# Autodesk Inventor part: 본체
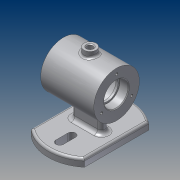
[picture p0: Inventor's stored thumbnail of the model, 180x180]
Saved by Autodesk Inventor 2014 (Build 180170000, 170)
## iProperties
Created: 2017-12
Part Number: 본체
Material: 알루미늄 6061
Document SubType Name: Modeling
Designer: user
Density: 2.71 g/cm^3
Appearance: 알루미늄 - 평지
Author: user
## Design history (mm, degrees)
sketch "스케치1"
  geometry: L1 (35, -42.426)-(35, 42.426); L2 (-35, 42.426)-(-35, -42.426); L3 (-35, 42.426)-(35, 42.426); A1 r 55 centre (0, 0) between (-35, -42.426) and (35, -42.426); A2 r 55 centre (0, 0) between (35, 42.426) and (-35, 42.426); 2 further points
  constraints: 6 end point, 4 point on circle, 2 centre point, 1 coincident, 1 midpoint, 1 parallel, 1 perpendicular, 1 vertical alignment
  dimensions: "d2" = 70 distance between parallel lines of L1 L2; "d3" = 55 radius of A2; "d4" = 55 radius of A1
extrude "돌출1" new body sketch "스케치1" distance "d5" = 10; taper "d6" = 0 deg
sketch "스케치2"
  geometry: L1 (0, 40)-(0, 24); L2 (-5, 40)-(-5, 24); L3 (5, 24)-(5, 40); L4 (0, -24)-(0, -40); L5 (-5, -24)-(-5, -40); L6 (5, -40)-(5, -24); A1 r 5 centre (0, 40) between (5, 40) and (-5, 40); A2 r 5 centre (0, 24) between (-5, 24) and (5, 24); A3 r 5 centre (0, -24) between (5, -24) and (-5, -24); A4 r 5 centre (0, -40) between (-5, -40) and (5, -40); 3 further points
  constraints: 16 end point, 8 point on circle, 8 tangent, 4 centre point, 3 equal length, 2 midpoint, 2 vertical alignment, 1 vertical
  dimensions: "d7" = 16 distance of L1.start L1.end; "d8" = 10 diameter of A2; "d9" = 16 distance of L4.start L4.end; "d10" = 5 radius of A4; "d11" = 24 distance of point (0, 0) L4.start; "d12" = 24 distance of point (0, 0) L1.end
extrude "돌출2" cut sketch "스케치2" distance "d13" = 10; taper "d14" = 0 deg
sketch "스케치3"
  geometry: L1 (-67.128, 62)-(67.128, 62); C1 r 30 at (0, 62); 2 further points
  constraints: 2 end point, 1 centre point, 1 coincident, 1 horizontal, 1 midpoint, 1 vertical alignment
  dimensions: "d15" = 62 distance from line of point (0, 0) L1; "d17" = 60 diameter of C1
extrude "돌출3" join sketch "스케치3" stored distance "d18" = 70; taper "d19" = 0 deg
node "작업 평면1"
sketch "스케치4"
  geometry: C1 r 8 at (0, 0); 1 further point
  constraints: 1 centre point, 1 coincident
  dimensions: "d21" = 16 diameter of C1
extrude "돌출4" join sketch "스케치4" stored distance "d22" = 70; taper "d23" = 0 deg
sketch "스케치5"
  geometry: L1 (-15, 0)-(15, 0); L2 (-15, -5)-(15, -5); L3 (15, 5)-(-15, 5); A1 r 5 centre (-15, 0) between (-15, 5) and (-15, -5); A2 r 5 centre (15, 0) between (15, -5) and (15, 5); 1 further point
  constraints: 8 end point, 4 point on circle, 4 tangent, 2 centre point, 1 horizontal, 1 midpoint, 1 parallel
  dimensions: "d24" = 15 distance of point (0, 0) L1.end; "d25" = 10 diameter of A2
extrude "돌출5" join sketch "스케치5" stored distance "d26" = 70; taper "d27" = 0 deg
sketch "스케치6"
  geometry: L1 (-78.249, 62)-(81.995, 62); L2 (-35, 92)-(-35, 32) reference; L3 (-35, 62)-(-23, 62); L4 (-23, 62)-(-23, 78); L5 (-23, 78)-(-35, 78); L6 (-35, 78)-(-35, 62); L7 (-23, 62)-(-20, 62); L8 (-20, 62)-(-20, 76); L9 (-20, 76)-(-23, 76); L10 (-23, 76)-(-23, 62); L11 (-20, 62)-(20, 62); L12 (20, 62)-(20, 87); L13 (20, 87)-(-20, 87); L14 (-20, 87)-(-20, 62); L15 (20, 62)-(23, 62); L16 (23, 62)-(23, 76); L17 (23, 76)-(20, 76); L18 (20, 76)-(20, 62); L19 (23, 62)-(35, 62); L20 (35, 62)-(35, 78); L21 (35, 78)-(23, 78); L22 (23, 78)-(23, 62); 1 further point
  constraints: 42 end point, 10 parallel, 6 horizontal, 5 perpendicular, 1 midpoint
  dimensions: "d28" = 62 distance from line of point (0, 0) L1; "d29" = 12 distance of L5.end L4.end; "d30" = 16 distance of L4.end L3.end; "d31" = 3 distance of L9.end L8.end; "d32" = 14 distance of L8.end L7.end; "d33" = 40 distance of L13.end L12.end; "d34" = 25 distance of L12.end L11.end; "d35" = 3 distance of L17.end L16.end; "d36" = 14 distance of L16.end L15.end; "d37" = 12 distance of L21.end L20.end; "d38" = 16 distance of L20.end L19.end
revolve "회전1" sketch "스케치6" stored, may be unused: angle "d39" = 90 deg
hole "구멍1" diameter "d42" = 8; stored, may be unused: countersink angle "d46" = 90 deg, drill point angle "d48" = 118 deg; dims "d40" = 10, "d41" = 10, "d43" = 6, "d44" = 4, "d45" = 2, "d47" = 50
sketch "스케치7"
  geometry: C1 r 16 at (0, 0) reference; C2 r 30 at (0, 0) reference; 2 further points
  constraints: 1 horizontal alignment
  dimensions: "d49" = 23 distance of point (-23, 0) C1.centre
hole "구멍2" sketch "스케치7" at (-23, 0) diameter "d50" = 3.459; stored, may be unused: countersink angle "d54" = 90 deg, drill point angle "d56" = 118 deg; dims "d51" = 8, "d52" = 4, "d53" = 2, "d55" = 10
node "작업 평면2"
sketch "스케치9"
  geometry: L1 (-20, -82)-(50, -82) reference; 2 further points
  constraints: 1 vertical alignment, 1 other
  dimensions: "d61" = 30 distance from line of L1 point (15, -52)
feature "엠보싱1" sketch "스케치9" dims "d2" = 70, "d3" = 55, "d4" = 55, "d62" = 0.5, "d63" = 0
fillet "모깎기1" dims "d64" = 0.3
fillet "모깎기2" dims "d65" = 3
fillet "모깎기3" dims "d66" = 5
fillet "모깎기4" dims "d67" = 3
chamfer "모따기1" distance "d68" = 1; stored, may be unused: second distance "d69" = 2, angle "d70" = 45 deg
node "솔리드1"
pattern_circular "원형 패턴1" dims angle "d58" = 360 deg
mirror "대칭1"
node "투영된 루프1"
other parameters: "d20" = 89, "d60" = 58.5
